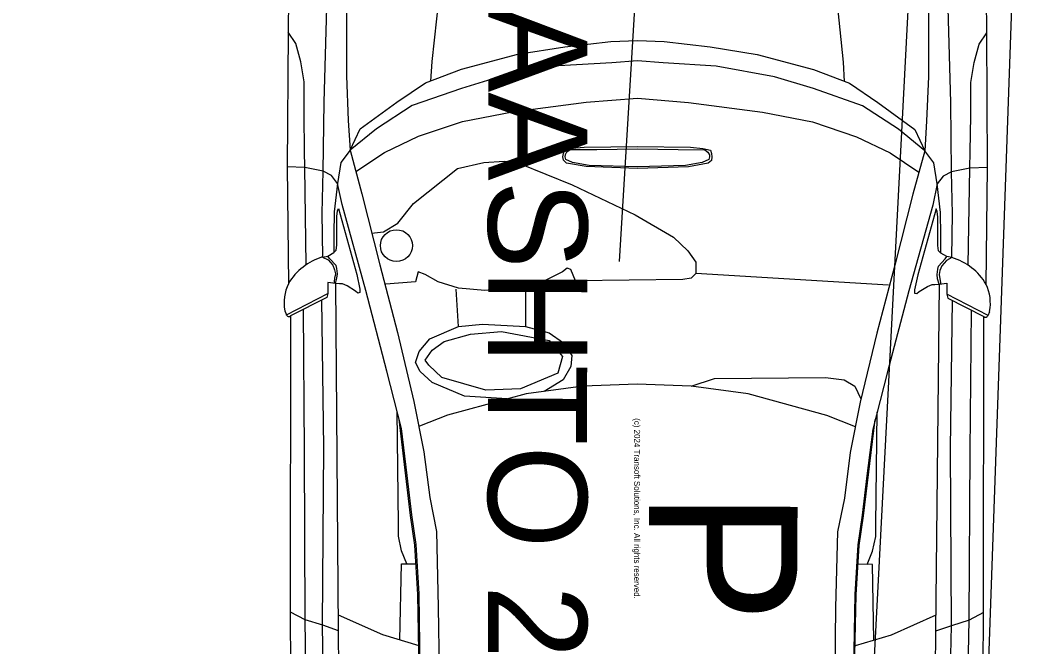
# Model space of a CAD drawing. Extents: x 17465868 to 18455672, y 7253752 to 7478845.
# Drawn here: x 18455112.18 to 18455122.36, y 7478450.16 to 7478456.49 of the extents above; entities that cross this region are included whole.
import ezdxf

# ---------------------------------------------------------------- set-up
doc = ezdxf.new("R2010")
doc.units = 0
for name, color, linetype in [('Clinton 225 CL Truss', 7, 'Continuous'), ('Clinton 225 Handrail', 7, 'Continuous'), ('Clinton 225 Metal Rail', 7, 'Continuous'), ('Dallas 126 CL Girder', 7, 'Continuous')]:
    doc.layers.add(name, color=color, linetype=linetype)

msp = doc.modelspace()

# ---------------------------------------------------------------- linework, layer by layer
at = {"layer": 'Clinton 225 CL Truss'}
for p, q in [((18455118.23, 7478454.047), (18455140.106, 7478819.122)), ((18455114.901, 7478457.608), (18455114.885, 7478456.365)), ((18455121.938, 7478456.359), (18455121.925, 7478457.601)), ((18455116.449, 7478457.123), (18455116.335, 7478456.067)), ((18455120.376, 7478457.12), (18455120.488, 7478456.063)), ((18455115.474, 7478456.771), (18455115.473, 7478455.924)), ((18455121.35, 7478456.765), (18455121.35, 7478455.918)), ((18455115.249, 7478455.659), (18455115.275, 7478456.612)), ((18455121.574, 7478455.653), (18455121.549, 7478456.606)), ((18455114.885, 7478456.365), (18455114.875, 7478455.006)), ((18455114.961, 7478456.25), (18455114.885, 7478456.365)), ((18455121.862, 7478456.244), (18455121.938, 7478456.359)), ((18455121.946, 7478454.999), (18455121.938, 7478456.359)), ((18455115.012, 7478456.065), (18455114.961, 7478456.25)), ((18455117.678, 7478456.217), (18455118.143, 7478456.27)), ((18455118.143, 7478456.27), (18455118.412, 7478456.281)), ((18455118.412, 7478456.281), (18455118.681, 7478456.27)), ((18455118.681, 7478456.27), (18455119.145, 7478456.215)), ((18455117.203, 7478456.142), (18455117.678, 7478456.217)), ((18455119.145, 7478456.215), (18455119.621, 7478456.139)), ((18455121.811, 7478456.059), (18455121.862, 7478456.244)), ((18455115.046, 7478455.862), (18455115.012, 7478456.065)), ((18455116.335, 7478456.067), (18455116.323, 7478455.871)), ((18455116.634, 7478455.991), (18455117.203, 7478456.142)), ((18455118.153, 7478456.055), (18455117.616, 7478456.023)), ((18455118.412, 7478456.075), (18455118.153, 7478456.055)), ((18455118.67, 7478456.054), (18455118.412, 7478456.075)), ((18455119.207, 7478456.021), (18455118.67, 7478456.054)), ((18455119.621, 7478456.139), (18455120.189, 7478455.988)), ((18455120.488, 7478456.063), (18455120.499, 7478455.867)), ((18455121.777, 7478455.855), (18455121.811, 7478456.059)), ((18455116.273, 7478455.852), (18455116.634, 7478455.991)), ((18455117.616, 7478456.023), (18455117.027, 7478455.916)), ((18455119.796, 7478455.913), (18455119.207, 7478456.021)), ((18455120.189, 7478455.988), (18455120.55, 7478455.848)), ((18455115.045, 7478455.526), (18455115.046, 7478455.862)), ((18455115.473, 7478455.924), (18455115.492, 7478455.471)), ((18455115.983, 7478455.658), (18455116.273, 7478455.852)), ((18455117.027, 7478455.916), (18455116.634, 7478455.797)), ((18455120.189, 7478455.794), (18455119.796, 7478455.913)), ((18455120.55, 7478455.848), (18455120.839, 7478455.653)), ((18455121.35, 7478455.918), (18455121.33, 7478455.465)), ((18455121.777, 7478455.52), (18455121.777, 7478455.855)), ((18455116.634, 7478455.797), (18455116.138, 7478455.625)), ((18455120.684, 7478455.621), (18455120.189, 7478455.794)), ((18455115.239, 7478454.961), (18455115.249, 7478455.659)), ((18455115.611, 7478455.389), (18455115.983, 7478455.658)), ((18455117.15, 7478455.56), (18455117.894, 7478455.656)), ((18455117.894, 7478455.656), (18455118.411, 7478455.698)), ((18455118.411, 7478455.698), (18455118.928, 7478455.655)), ((18455118.928, 7478455.655), (18455119.672, 7478455.557)), ((18455120.839, 7478455.653), (18455121.211, 7478455.383)), ((18455121.582, 7478454.955), (18455121.574, 7478455.653)), ((18455116.138, 7478455.625), (18455115.776, 7478455.389)), ((18455116.644, 7478455.463), (18455117.15, 7478455.56)), ((18455119.672, 7478455.557), (18455120.178, 7478455.46)), ((18455121.046, 7478455.384), (18455120.684, 7478455.621)), ((18455115.051, 7478455.164), (18455115.045, 7478455.526)), ((18455115.492, 7478455.471), (18455115.51, 7478455.172)), ((18455116.2, 7478455.313), (18455116.644, 7478455.463)), ((18455120.178, 7478455.46), (18455120.622, 7478455.309)), ((18455121.33, 7478455.465), (18455121.312, 7478455.167)), ((18455121.77, 7478455.158), (18455121.777, 7478455.52)), ((18455115.51, 7478455.172), (18455115.611, 7478455.389)), ((18455115.776, 7478455.389), (18455115.51, 7478455.172)), ((18455121.312, 7478455.167), (18455121.046, 7478455.384)), ((18455121.211, 7478455.383), (18455121.312, 7478455.167)), ((18455115.859, 7478455.151), (18455116.2, 7478455.313)), ((18455120.622, 7478455.309), (18455120.963, 7478455.147)), ((18455115.053, 7478454.997), (18455115.051, 7478455.164)), ((18455115.51, 7478455.172), (18455115.417, 7478455.049)), ((18455115.51, 7478455.172), (18455115.629, 7478454.733)), ((18455115.569, 7478454.958), (18455115.859, 7478455.151)), ((18455117.659, 7478455.106), (18455117.663, 7478455.14)), ((18455117.663, 7478455.14), (18455117.674, 7478455.174)), ((18455117.674, 7478455.174), (18455117.75, 7478455.193)), ((18455117.681, 7478455.106), (18455117.685, 7478455.128)), ((18455117.685, 7478455.128), (18455117.699, 7478455.155)), ((18455117.699, 7478455.155), (18455117.732, 7478455.178)), ((18455117.732, 7478455.178), (18455118, 7478455.181)), ((18455117.75, 7478455.193), (18455117.873, 7478455.204)), ((18455117.873, 7478455.204), (18455118.411, 7478455.211)), ((18455118, 7478455.181), (18455118.411, 7478455.185)), ((18455118.411, 7478455.211), (18455118.948, 7478455.203)), ((18455118.411, 7478455.185), (18455118.821, 7478455.18)), ((18455118.821, 7478455.18), (18455119.09, 7478455.176)), ((18455118.948, 7478455.203), (18455119.071, 7478455.191)), ((18455119.071, 7478455.191), (18455119.148, 7478455.173)), ((18455119.09, 7478455.176), (18455119.122, 7478455.154)), ((18455119.122, 7478455.154), (18455119.137, 7478455.127)), ((18455119.137, 7478455.127), (18455119.14, 7478455.104)), ((18455119.148, 7478455.173), (18455119.158, 7478455.138)), ((18455119.158, 7478455.138), (18455119.162, 7478455.104)), ((18455120.963, 7478455.147), (18455121.252, 7478454.952)), ((18455121.312, 7478455.167), (18455121.191, 7478454.728)), ((18455121.404, 7478455.044), (18455121.312, 7478455.167)), ((18455121.768, 7478454.99), (18455121.77, 7478455.158)), ((18455115.417, 7478455.049), (18455115.383, 7478454.837)), ((18455116.595, 7478454.987), (18455116.86, 7478455.049)), ((18455116.86, 7478455.049), (18455117.064, 7478455.062)), ((18455117.064, 7478455.062), (18455117.221, 7478455.037)), ((18455117.221, 7478455.037), (18455117.751, 7478454.822)), ((18455117.663, 7478455.072), (18455117.659, 7478455.106)), ((18455117.695, 7478455.041), (18455117.663, 7478455.072)), ((18455117.688, 7478455.079), (18455117.681, 7478455.106)), ((18455117.757, 7478455.049), (18455117.688, 7478455.079)), ((18455117.895, 7478455.007), (18455117.695, 7478455.041)), ((18455117.924, 7478455.019), (18455117.757, 7478455.049)), ((18455119.064, 7478455.048), (18455118.897, 7478455.018)), ((18455119.126, 7478455.04), (18455118.926, 7478455.006)), ((18455119.133, 7478455.078), (18455119.064, 7478455.048)), ((18455119.158, 7478455.07), (18455119.126, 7478455.04)), ((18455119.14, 7478455.104), (18455119.133, 7478455.078)), ((18455119.162, 7478455.104), (18455119.158, 7478455.07)), ((18455121.438, 7478454.832), (18455121.404, 7478455.044)), ((18455115.053, 7478454.997), (18455114.875, 7478455.006)), ((18455114.875, 7478455.006), (18455114.888, 7478453.824)), ((18455115.239, 7478454.961), (18455115.053, 7478454.997)), ((18455115.068, 7478454.016), (18455115.053, 7478454.997)), ((18455115.23, 7478454.536), (18455115.239, 7478454.961)), ((18455115.324, 7478454.917), (18455115.239, 7478454.961)), ((18455116.149, 7478454.635), (18455116.595, 7478454.987)), ((18455118.411, 7478454.988), (18455117.895, 7478455.007)), ((18455118.411, 7478455.003), (18455117.924, 7478455.019)), ((18455118.897, 7478455.018), (18455118.411, 7478455.003)), ((18455118.926, 7478455.006), (18455118.411, 7478454.988)), ((18455121.582, 7478454.955), (18455121.497, 7478454.911)), ((18455121.768, 7478454.99), (18455121.582, 7478454.955)), ((18455121.59, 7478454.53), (18455121.582, 7478454.955)), ((18455121.751, 7478454.01), (18455121.768, 7478454.99)), ((18455121.946, 7478454.999), (18455121.768, 7478454.99)), ((18455121.931, 7478453.818), (18455121.946, 7478454.999)), ((18455115.383, 7478454.837), (18455115.324, 7478454.917)), ((18455115.383, 7478454.837), (18455115.351, 7478454.549)), ((18455115.429, 7478454.623), (18455115.383, 7478454.837)), ((18455117.751, 7478454.822), (18455118.389, 7478454.52)), ((18455121.438, 7478454.832), (18455121.392, 7478454.617)), ((18455121.497, 7478454.911), (18455121.438, 7478454.832)), ((18455121.47, 7478454.543), (18455121.438, 7478454.832)), ((18455115.629, 7478454.733), (18455115.809, 7478454.015)), ((18455121.191, 7478454.728), (18455121.01, 7478454.01)), ((18455115.669, 7478453.757), (18455115.429, 7478454.623)), ((18455115.992, 7478454.435), (18455116.149, 7478454.635)), ((18455121.392, 7478454.617), (18455121.15, 7478453.751)), ((18455115.234, 7478454.097), (18455115.23, 7478454.536)), ((18455115.351, 7478454.549), (18455115.346, 7478454.318)), ((18455115.378, 7478454.502), (18455115.383, 7478454.56)), ((18455115.383, 7478454.56), (18455115.392, 7478454.584)), ((18455115.392, 7478454.584), (18455115.578, 7478453.919)), ((18455118.389, 7478454.52), (18455118.774, 7478454.294)), ((18455121.428, 7478454.579), (18455121.241, 7478453.914)), ((18455121.437, 7478454.554), (18455121.428, 7478454.579)), ((18455121.442, 7478454.496), (18455121.437, 7478454.554)), ((18455121.473, 7478454.313), (18455121.47, 7478454.543)), ((18455121.586, 7478454.091), (18455121.59, 7478454.53)), ((18455115.378, 7478454.215), (18455115.378, 7478454.502)), ((18455115.847, 7478454.347), (18455115.992, 7478454.435)), ((18455121.442, 7478454.21), (18455121.442, 7478454.496)), ((18455115.346, 7478454.318), (18455115.346, 7478454.139)), ((18455115.727, 7478454.334), (18455115.847, 7478454.347)), ((18455121.473, 7478454.133), (18455121.473, 7478454.313)), ((18455115.368, 7478454.162), (18455115.378, 7478454.215)), ((18455118.774, 7478454.294), (18455118.918, 7478454.155)), ((18455121.451, 7478454.156), (18455121.442, 7478454.21)), ((18455115.285, 7478454.104), (18455115.345, 7478454.138)), ((18455115.345, 7478454.138), (18455115.368, 7478454.162)), ((18455118.918, 7478454.155), (18455119.002, 7478454.042)), ((18455121.474, 7478454.132), (18455121.451, 7478454.156)), ((18455121.535, 7478454.098), (18455121.474, 7478454.132)), ((18455115.233, 7478454.094), (18455115.285, 7478454.104)), ((18455115.233, 7478454.094), (18455115.289, 7478454.065)), ((18455115.303, 7478454.08), (18455115.285, 7478454.104)), ((18455115.289, 7478454.065), (18455115.336, 7478454.012)), ((18455115.368, 7478454.007), (18455115.303, 7478454.08)), ((18455115.336, 7478454.012), (18455115.354, 7478453.963)), ((18455115.378, 7478453.978), (18455115.368, 7478454.007)), ((18455115.809, 7478454.015), (18455115.989, 7478453.331)), ((18455119.002, 7478454.042), (18455119.002, 7478453.929)), ((18455121.01, 7478454.01), (18455120.829, 7478453.326)), ((18455121.451, 7478454.001), (18455121.516, 7478454.074)), ((18455121.484, 7478454.006), (18455121.465, 7478453.957)), ((18455121.53, 7478454.059), (18455121.484, 7478454.006)), ((18455121.516, 7478454.074), (18455121.535, 7478454.098)), ((18455121.586, 7478454.088), (18455121.53, 7478454.059)), ((18455121.586, 7478454.088), (18455121.535, 7478454.098)), ((18455115.354, 7478453.963), (18455115.364, 7478453.924)), ((18455115.364, 7478453.924), (18455115.354, 7478453.88)), ((18455115.377, 7478453.88), (18455115.382, 7478453.924)), ((18455115.382, 7478453.924), (18455115.378, 7478453.978)), ((18455115.578, 7478453.919), (18455115.61, 7478453.769)), ((18455116.196, 7478453.944), (18455116.172, 7478453.844)), ((18455116.268, 7478453.919), (18455116.196, 7478453.944)), ((18455116.401, 7478453.844), (18455116.268, 7478453.919)), ((18455117.654, 7478453.943), (18455117.425, 7478453.83)), ((18455117.702, 7478453.981), (18455117.654, 7478453.943)), ((18455117.738, 7478453.968), (18455117.702, 7478453.981)), ((18455117.786, 7478453.855), (18455117.738, 7478453.968)), ((18455119.002, 7478453.929), (18455118.954, 7478453.879)), ((18455120.944, 7478453.809), (18455119.002, 7478453.929)), ((18455121.241, 7478453.914), (18455121.209, 7478453.763)), ((18455121.437, 7478453.918), (18455121.442, 7478453.972)), ((18455121.441, 7478453.875), (18455121.437, 7478453.918)), ((18455121.442, 7478453.972), (18455121.451, 7478454.001)), ((18455121.465, 7478453.957), (18455121.456, 7478453.918)), ((18455121.456, 7478453.918), (18455121.465, 7478453.875)), ((18455115.362, 7478453.826), (18455115.284, 7478453.837)), ((18455115.284, 7478453.837), (18455115.284, 7478453.725)), ((18455115.349, 7478453.842), (18455115.348, 7478453.828)), ((18455115.354, 7478453.88), (18455115.349, 7478453.842)), ((18455115.362, 7478453.826), (18455115.377, 7478453.88)), ((18455115.362, 7478453.826), (18455115.391, 7478450.322)), ((18455115.405, 7478453.822), (18455115.362, 7478453.826)), ((18455115.433, 7478453.822), (18455115.405, 7478453.822)), ((18455115.48, 7478453.803), (18455115.433, 7478453.822)), ((18455115.564, 7478453.749), (18455115.48, 7478453.803)), ((18455116.172, 7478453.844), (18455115.871, 7478453.819)), ((18455116.606, 7478453.781), (18455116.401, 7478453.844)), ((18455117.425, 7478453.83), (18455117.244, 7478453.793)), ((18455118.87, 7478453.866), (18455117.786, 7478453.855)), ((18455118.954, 7478453.879), (18455118.87, 7478453.866)), ((18455121.339, 7478453.797), (18455121.386, 7478453.816)), ((18455121.386, 7478453.816), (18455121.414, 7478453.816)), ((18455121.414, 7478453.816), (18455121.457, 7478453.82)), ((18455121.457, 7478453.82), (18455121.421, 7478450.317)), ((18455121.457, 7478453.82), (18455121.441, 7478453.875)), ((18455121.457, 7478453.82), (18455121.535, 7478453.831)), ((18455121.465, 7478453.875), (18455121.469, 7478453.836)), ((18455121.469, 7478453.836), (18455121.471, 7478453.822)), ((18455121.535, 7478453.831), (18455121.534, 7478453.719)), ((18455114.868, 7478453.51), (18455115.284, 7478453.725)), ((18455115.284, 7478453.725), (18455115.275, 7478453.686)), ((18455115.587, 7478453.73), (18455115.564, 7478453.749)), ((18455115.61, 7478453.735), (18455115.587, 7478453.73)), ((18455115.61, 7478453.769), (18455115.61, 7478453.735)), ((18455115.882, 7478452.941), (18455115.669, 7478453.757)), ((18455116.605, 7478453.391), (18455116.581, 7478453.768)), ((18455116.871, 7478453.755), (18455116.606, 7478453.781)), ((18455117.244, 7478453.793), (18455116.871, 7478453.755)), ((18455117.28, 7478453.793), (18455117.28, 7478453.391)), ((18455121.15, 7478453.751), (18455120.935, 7478452.936)), ((18455121.209, 7478453.763), (18455121.209, 7478453.729)), ((18455121.209, 7478453.729), (18455121.232, 7478453.724)), ((18455121.232, 7478453.724), (18455121.255, 7478453.744)), ((18455121.255, 7478453.744), (18455121.339, 7478453.797)), ((18455121.534, 7478453.719), (18455121.544, 7478453.68)), ((18455121.95, 7478453.504), (18455121.534, 7478453.719)), ((18455115.275, 7478453.686), (18455114.909, 7478453.499)), ((18455115.245, 7478452.169), (18455115.225, 7478453.661)), ((18455121.544, 7478453.68), (18455121.909, 7478453.492)), ((18455121.571, 7478452.163), (18455121.593, 7478453.655)), ((18455114.851, 7478453.551), (18455114.868, 7478453.51)), ((18455114.872, 7478453.504), (18455114.878, 7478453.498)), ((18455114.909, 7478453.499), (18455114.906, 7478450.51)), ((18455115.036, 7478453.563), (18455115.045, 7478452.136)), ((18455121.771, 7478452.13), (18455121.783, 7478453.557)), ((18455121.94, 7478453.491), (18455121.946, 7478453.498)), ((18455121.95, 7478453.504), (18455121.967, 7478453.544)), ((18455116.605, 7478453.391), (18455116.846, 7478453.416)), ((18455116.846, 7478453.416), (18455117.28, 7478453.391)), ((18455121.906, 7478450.503), (18455121.909, 7478453.492)), ((18455115.989, 7478453.331), (18455116.155, 7478452.634)), ((18455116.316, 7478453.266), (18455116.605, 7478453.391)), ((18455116.461, 7478453.241), (18455116.726, 7478453.316)), ((18455116.726, 7478453.316), (18455117.039, 7478453.341)), ((18455117.039, 7478453.341), (18455117.52, 7478453.252)), ((18455117.28, 7478453.391), (18455117.52, 7478453.328)), ((18455117.52, 7478453.328), (18455117.665, 7478453.227)), ((18455120.829, 7478453.326), (18455120.661, 7478452.629)), ((18455116.208, 7478453.14), (18455116.316, 7478453.266)), ((18455116.34, 7478453.153), (18455116.461, 7478453.241)), ((18455117.52, 7478453.252), (18455117.653, 7478453.089)), ((18455117.665, 7478453.227), (18455117.749, 7478453.101)), ((18455116.171, 7478453.027), (18455116.208, 7478453.14)), ((18455116.268, 7478453.052), (18455116.34, 7478453.153)), ((18455117.749, 7478453.101), (18455117.737, 7478452.988)), ((18455116.219, 7478452.939), (18455116.171, 7478453.027)), ((18455116.304, 7478453.002), (18455116.268, 7478453.052)), ((18455116.436, 7478452.876), (18455116.304, 7478453.002)), ((18455117.653, 7478453.089), (18455117.607, 7478452.921)), ((18455117.737, 7478452.988), (18455117.66, 7478452.855)), ((18455116.028, 7478452.362), (18455115.882, 7478452.941)), ((18455116.34, 7478452.826), (18455116.219, 7478452.939)), ((18455117.607, 7478452.921), (18455117.231, 7478452.762)), ((18455120.935, 7478452.936), (18455120.788, 7478452.357)), ((18455116.665, 7478452.688), (18455116.34, 7478452.826)), ((18455116.882, 7478452.75), (18455116.436, 7478452.876)), ((18455117.863, 7478452.789), (18455117.289, 7478452.713)), ((18455117.66, 7478452.855), (18455117.468, 7478452.737)), ((18455118.408, 7478452.81), (18455117.863, 7478452.789)), ((18455118.953, 7478452.788), (18455118.408, 7478452.81)), ((18455118.953, 7478452.788), (18455119.19, 7478452.867)), ((18455119.528, 7478452.711), (18455118.953, 7478452.788)), ((18455119.19, 7478452.867), (18455120.311, 7478452.878)), ((18455120.311, 7478452.878), (18455120.499, 7478452.853)), ((18455120.499, 7478452.853), (18455120.605, 7478452.791)), ((18455120.605, 7478452.791), (18455120.667, 7478452.661)), ((18455117.289, 7478452.713), (18455116.494, 7478452.496)), ((18455117.096, 7478452.661), (18455116.665, 7478452.688)), ((18455117.231, 7478452.762), (18455116.882, 7478452.75)), ((18455120.322, 7478452.492), (18455119.528, 7478452.711)), ((18455116.155, 7478452.634), (18455116.255, 7478452.125)), ((18455120.661, 7478452.629), (18455120.56, 7478452.121)), ((18455115.998, 7478451.392), (18455115.984, 7478452.536)), ((18455116.494, 7478452.496), (18455116.212, 7478452.387)), ((18455120.612, 7478452.38), (18455120.322, 7478452.492)), ((18455120.816, 7478451.388), (18455120.832, 7478452.531)), ((18455116.12, 7478451.483), (18455116.004, 7478452.458)), ((18455120.694, 7478451.479), (18455120.812, 7478452.454)), ((18455116.088, 7478451.888), (18455116.028, 7478452.362)), ((18455120.788, 7478452.357), (18455120.727, 7478451.883)), ((18455115.045, 7478452.136), (18455115.054, 7478450.433)), ((18455115.233, 7478450.378), (18455115.245, 7478452.169)), ((18455116.255, 7478452.125), (18455116.315, 7478451.664)), ((18455120.56, 7478452.121), (18455120.5, 7478451.66)), ((18455121.58, 7478450.371), (18455121.571, 7478452.163)), ((18455121.759, 7478450.426), (18455121.771, 7478452.13)), ((18455116.134, 7478451.49), (18455116.088, 7478451.888)), ((18455120.727, 7478451.883), (18455120.68, 7478451.486)), ((18455116.315, 7478451.664), (18455116.383, 7478451.323)), ((18455120.5, 7478451.66), (18455120.431, 7478451.32)), ((18455116.164, 7478451.184), (18455116.12, 7478451.483)), ((18455116.177, 7478451.191), (18455116.134, 7478451.49)), ((18455120.68, 7478451.486), (18455120.637, 7478451.187)), ((18455120.65, 7478451.18), (18455120.694, 7478451.479)), ((18455115.998, 7478451.274), (18455115.998, 7478451.392)), ((18455120.816, 7478451.27), (18455120.816, 7478451.388)), ((18455116.029, 7478451.128), (18455115.998, 7478451.274)), ((18455116.383, 7478451.323), (18455116.401, 7478450.559)), ((18455120.431, 7478451.32), (18455120.411, 7478450.555)), ((18455120.785, 7478451.123), (18455120.816, 7478451.27)), ((18455116.194, 7478450.685), (18455116.164, 7478451.184)), ((18455116.206, 7478450.692), (18455116.177, 7478451.191)), ((18455120.637, 7478451.187), (18455120.607, 7478450.687)), ((18455120.619, 7478450.681), (18455120.65, 7478451.18)), ((18455116.084, 7478450.995), (18455116.029, 7478451.128)), ((18455120.729, 7478450.99), (18455120.785, 7478451.123)), ((18455116.014, 7478450.228), (18455116.029, 7478450.995)), ((18455116.029, 7478450.995), (18455116.172, 7478450.995)), ((18455120.785, 7478450.99), (18455120.641, 7478450.991)), ((18455120.798, 7478450.224), (18455120.785, 7478450.99)), ((18455116.22, 7478449.387), (18455116.194, 7478450.685)), ((18455116.225, 7478449.58), (18455116.206, 7478450.692)), ((18455120.607, 7478450.687), (18455120.586, 7478449.576)), ((18455120.591, 7478449.382), (18455120.619, 7478450.681)), ((18455116.401, 7478450.559), (18455116.419, 7478448.897)), ((18455120.411, 7478450.555), (18455120.39, 7478448.893)), ((18455114.906, 7478450.51), (18455115.054, 7478450.433)), ((18455114.906, 7478450.51), (18455114.913, 7478449.271)), ((18455115.389, 7478450.482), (18455115.839, 7478450.281)), ((18455121.423, 7478450.476), (18455120.973, 7478450.276)), ((18455121.906, 7478450.503), (18455121.759, 7478450.426)), ((18455121.897, 7478449.264), (18455121.906, 7478450.503)), ((18455115.054, 7478450.433), (18455115.068, 7478449.444)), ((18455115.054, 7478450.433), (18455115.233, 7478450.378)), ((18455115.246, 7478449.444), (18455115.233, 7478450.378)), ((18455115.233, 7478450.378), (18455115.391, 7478450.322)), ((18455121.58, 7478450.371), (18455121.421, 7478450.317)), ((18455121.565, 7478449.438), (18455121.58, 7478450.371)), ((18455121.759, 7478450.426), (18455121.58, 7478450.371)), ((18455121.742, 7478449.438), (18455121.759, 7478450.426)), ((18455115.391, 7478450.322), (18455115.4, 7478449.247)), ((18455115.839, 7478450.281), (18455116.204, 7478450.171)), ((18455120.973, 7478450.276), (18455120.608, 7478450.167)), ((18455121.421, 7478450.317), (18455121.41, 7478449.241))]:
    msp.add_line(p, q, dxfattribs=at)
for centre, radius, start, end in [((18455115.399, 7478453.527), 0.591, 106.2779, 149.7519), ((18455121.419, 7478453.521), 0.591, 30.1393, 73.6133), ((18455115.289, 7478453.631), 0.445, 154.2176, 190.3459), ((18455121.529, 7478453.625), 0.445, 349.5453, 25.6736), ((18455114.886, 7478453.518), 0.019, 202.7707, 223.8405), ((18455114.893, 7478453.516), 0.0236, 230.107, 311.6042), ((18455078.328, 7478418.538), 50.578, 43.72593027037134, 43.72593071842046), ((18455121.933, 7478453.511), 0.0183, 315.6007, 337.5705), ((18455121.925, 7478453.51), 0.0236, 228.287, 309.7842)]:
    msp.add_arc(centre, radius, start, end, dxfattribs=at)
msp.add_ellipse((18455115.978, 7478454.209), major_axis=(-0.162, 0), ratio=0.990086, dxfattribs=at)
msp.add_ellipse((18455120.841, 7478454.205), major_axis=(-0.162, 0), ratio=0.990086, start_param=4.712389, end_param=4.712389, dxfattribs=at)
at = {"layer": 'Clinton 225 Handrail'}
msp.add_line((18455118.562, 7478354.048), (18455135.011, 7478819.105), dxfattribs=at)
at = {"layer": 'Clinton 225 Metal Rail'}
msp.add_line((18455118.396, 7478404.048), (18455140.106, 7478819.122), dxfattribs=at)
at = {"layer": 'Dallas 126 CL Girder'}
for radius in [15064.793, 15052.793, 15040.793, 15028.793, 15018.793, 14988.793, 14978.793]:
    msp.add_arc((18458471.778, 7463759.052), radius, 101.0668789, 104.665109, dxfattribs=at)

# ---------------------------------------------------------------- texts
at = {"layer": 'Clinton 225 CL Truss'}
for s, height, p in [('AASHTO 2018 (US)', 1, (18455116.907, 7478456.65)), ('(c) 2024 Transoft Solutions, Inc. All rights reserved.', 0.06, (18455118.378, 7478452.466)), ('P', 1.5, (18455118.527, 7478451.737))]:
    msp.add_text(s, height=height, rotation=269.9456, dxfattribs=at).set_placement(p)

doc.saveas('drawing.dxf')
